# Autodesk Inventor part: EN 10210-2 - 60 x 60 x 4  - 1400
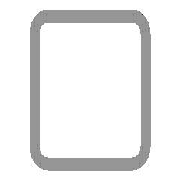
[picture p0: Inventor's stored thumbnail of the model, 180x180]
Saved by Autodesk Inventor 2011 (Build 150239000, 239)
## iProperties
IsCustomPart: 1
Created: 2010-02
Part Number: EN 10210-2 - 60 x 60 x 4  - 1400
Material: Steel, Mild
Description: Tube 60*60*4
Document SubType Name: Modeling
Standard: DIN
Designer: PC
Standard Revision: 1997
Standards Organization: DIN
Language: en-US
Size Designation: 60 x 60 x 4
Categories: <MemberInstance><Categories><Category DisplayName="Structural Shapes" InternalName="089c4875-fa83-4c05-b084-43b9cc11f5ed" Mnemonic="GRDR"><CategoryParameter Dis
Stock Number: 60 x 60 x 4
Density: 7.86 g/cm^3
_CCFamilyMember: 20
_CCFamilyDisplayName: DIN EN 10219-2 (Square Hollow Section - Cold Formed) - Cold formed welded structural hollow sections of non-alloy and fine grain structural steel
_FrameMemberDoc: Frame Member File
_Version: 15.0.0
_GetPNFromCC: 1
G_L: 1400.000 mm
G_W: 60.000 mm
G_H: 60.000 mm
Author: PC
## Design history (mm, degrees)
node "Start plane"
node "End plane"
sketch "Sketch"
  geometry: L1 (-30, -22)-(-30, 22); L2 (-22, 30)-(22, 30); L3 (30, 22)-(30, -22); L4 (22, -30)-(-22, -30); L5 (-22, 26)-(22, 26); L6 (26, 22)-(26, -22); L7 (22, -26)-(-22, -26); L8 (-26, -22)-(-26, 22); L9 (0, 44.32)-(0, -44.32) reference; L10 (-44.32, 0)-(44.32, 0) reference; A1 r 8 centre (-22, -22) between (-30, -22) and (-22, -30); A2 r 8 centre (-22, 22) between (-22, 30) and (-30, 22); A3 r 8 centre (22, 22) between (30, 22) and (22, 30); A4 r 8 centre (22, -22) between (22, -30) and (30, -22); A5 r 4 centre (-22, 22) between (-22, 26) and (-26, 22); A6 r 4 centre (22, 22) between (26, 22) and (22, 26); A7 r 4 centre (22, -22) between (22, -26) and (26, -22); A8 r 4 centre (-22, -22) between (-26, -22) and (-22, -26)
  constraints: 16 end point, 16 point on circle, 8 centre point, 8 tangent, 4 parallel, 3 equal radius, 2 perpendicular, 7 other
  dimensions: "d7" = 8 radius of A1 (= G_IR); "d10" = 60 distance between parallel lines of L2 L4 (= G_H); "d11" = 60 distance between parallel lines of L1 L3 (= G_W); "d12" = 4 distance between parallel lines of L3 L6 (= G_T); "d15" = 30 distance between parallel lines of L2 L10 (= 0.5 x d10); "d16" = 30 distance between parallel lines of L9 L3 (= 0.5 x d11)
extrude "Body" new body sketch "Sketch" stored distance "d3" = 1400 (= G_L); taper "d4" = 0 deg
node "Driven Length"
  sketch "Sketch3"
    geometry: L1 (0, 0)-(10, 0) reference
    constraints: 2 end point, 1 horizontal
  workplane "Work Plane3"
  sketch "Sketch4"
    geometry: L1 (-2, 0)-(12, 0) reference; L2 (-2, 1400)-(12, 1400) reference
    dimensions: "d18" = 1400 distance between parallel lines of L1 L2 (derived)
body "Solid1"
other parameters: "G_W" = 60 [user parameter; used in 1 equation term], "G_H" = 60 [user parameter; used in 1 equation term], "G_T" = 4 [user parameter; used in 1 equation term], "G_IR" = 8 [user parameter; used in 1 equation term], "G_L" = 1400 (= d18) [user parameter; used in 1 equation term], "G_OFFSET_START" = 0 [user parameter; used in 1 equation term], "G_OFFSET_END" = 0 [user parameter; used in 1 equation term], "d13" = 0 (computed from G_OFFSET_START), "d17" = 90 deg
